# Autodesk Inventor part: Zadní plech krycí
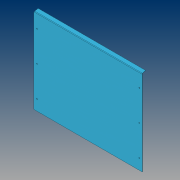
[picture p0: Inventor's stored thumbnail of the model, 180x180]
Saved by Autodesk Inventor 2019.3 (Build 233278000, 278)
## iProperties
Created: 2019-03
Part Number: Zadní plech krycí
Material: Ocel, měkká, svařovaná
Document SubType Name: Plech
Designer: B-hon
Density: 7.85 g/cm^3
Sheet Metal Rule: Výchozí_mm
Appearance: Tyrkysová
Author: B-hon
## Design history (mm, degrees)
node "Plocha1"
  sketch "Náčrt1"
    geometry: L1 (-357, 280)-(357, 280); L2 (357, 280)-(357, -280); L3 (357, -280)-(-357, -280); L4 (-357, -280)-(-357, 280); L5 (-357, 280)-(357, -280); L6 (357, 280)-(-357, -280); 1 further point
    constraints: 12 end point, 2 midpoint, 2 parallel, 1 horizontal, 1 perpendicular
    dimensions: "d0" = 714 distance of L2.end L3.end; "d1" = 560 distance of L1.end L2.end
node "Obruba1"
sketch "Náčrt3"
  geometry: L1 (-5.559, 15.009)-(26.35, 15.009); L2 (26.35, 15.009)-(26.35, -1); L3 (26.35, -1)-(-5.559, -1); L4 (-5.559, -1)-(-5.559, 15.009); L5 (2, 0)-(0, 0) reference; 1 further point
  constraints: 8 end point, 2 parallel, 1 horizontal, 1 perpendicular
  dimensions: "d13" = 1 distance between parallel lines of L5 L3
extrude "Vysunutí1" cut sketch "Náčrt3" distance "d14" = 3; taper "d15" = 0 deg
sketch "Náčrt5"
  geometry: L1 (-28.399, 555.931)-(8.562, 555.931); L2 (8.562, 555.931)-(8.562, 570.786); L3 (8.562, 570.786)-(-28.399, 570.786); L4 (-28.399, 570.786)-(-28.399, 555.931); L5 (2, 556.931)-(0, 556.931) reference; 1 further point
  constraints: 8 end point, 2 parallel, 1 horizontal, 1 perpendicular
  dimensions: "d16" = 1 distance between parallel lines of L5 L1
extrude "Vysunutí2" cut sketch "Náčrt5" distance "d17" = 3; taper "d18" = 0 deg
sketch "Náčrt6"
  geometry: L1 (357, 275.931)-(357, -280) reference; L2 (357, -280)-(-357, -280) reference; 2 further points
  dimensions: "d19" = 20 distance from line of L1 point (337, -210); "d20" = 70 distance from line of L2 point (337, -210)
hole "Díra1" sketch "Náčrt6" at (337, -210) diameter "d21" = 6.5; stored, may be unused: countersink angle "d25" = 90 deg, drill point angle "d27" = 118 deg; dims "d22" = 6, "d23" = 4, "d24" = 2, "d26" = 2 (= Tloušťka)
pattern_linear "Obdélníkové pole1" dims "d30" = 674, "d33" = 200
node "Těleso1"
feature "Deska1" dims "d2" = 2 (= Tloušťka)
sketch "Náčrt2"
  geometry: L1 through (357, 0) direction (-1, 0); L2 through (0, -12.5) direction (-2.58e-17, -1); L3 (0, -25)-(714, -25); L4 (714, -25)-(714, 0)
  constraints: 6 end point, 1 horizontal, 1 perpendicular, 1 vertical
feature "Deska2" dims "d2" = 2 (= Tloušťka), "d3" = 2 (= ŠířkaVýštipu), "d4" = 1 (= HloubkaVýštipu), "d5" = 4 (= MinimálníZbytek), "d6" = 2 (= PřechodovýPoloměr), "d7" = 25, "d8" = 75 deg, "d9" = 2 (= PoloměrOhybu), "d10" = 8 (= VelikostRohovéhoVýštipu), "d11" = 2 (= VelikostMezery), "d12" = 2 (= VelikostJacobihoPoloměru), "MezeraVystřižení" = 0.01
feature "Ohyb1" dims "d2" = 2 (= Tloušťka), "d3" = 2 (= ŠířkaVýštipu), "d4" = 1 (= HloubkaVýštipu), "d5" = 4 (= MinimálníZbytek), "d6" = 2 (= PřechodovýPoloměr), "d7" = 25, "d8" = 75 deg, "d9" = 2 (= PoloměrOhybu), "MezeraVystřižení" = 0.01
feature "Roh1" dims "d7" = 25, "d8" = 75 deg, "d10" = 8 (= VelikostRohovéhoVýštipu), "d11" = 2 (= VelikostMezery), "d12" = 2 (= VelikostJacobihoPoloměru)
other parameters: "Tloušťka" = 2 (derived), "KSoučinitel" = 4.4, "PoloměrOhybu" = 2 (= Tloušťka), "ŠířkaVýštipu" = 2 (= Tloušťka), "HloubkaVýštipu" = 1 (= 0.5 x Tloušťka), "VelikostRohovéhoVýštipu" = 8 (= 4 x Tloušťka), "MinimálníZbytek" = 4 (= 2 x Tloušťka), "PřechodovýPoloměr" = 2 (= PoloměrOhybu), "VelikostJacobihoPoloměru" = 2 (= PoloměrOhybu), "VelikostMezery" = 2 (= Tloušťka)
